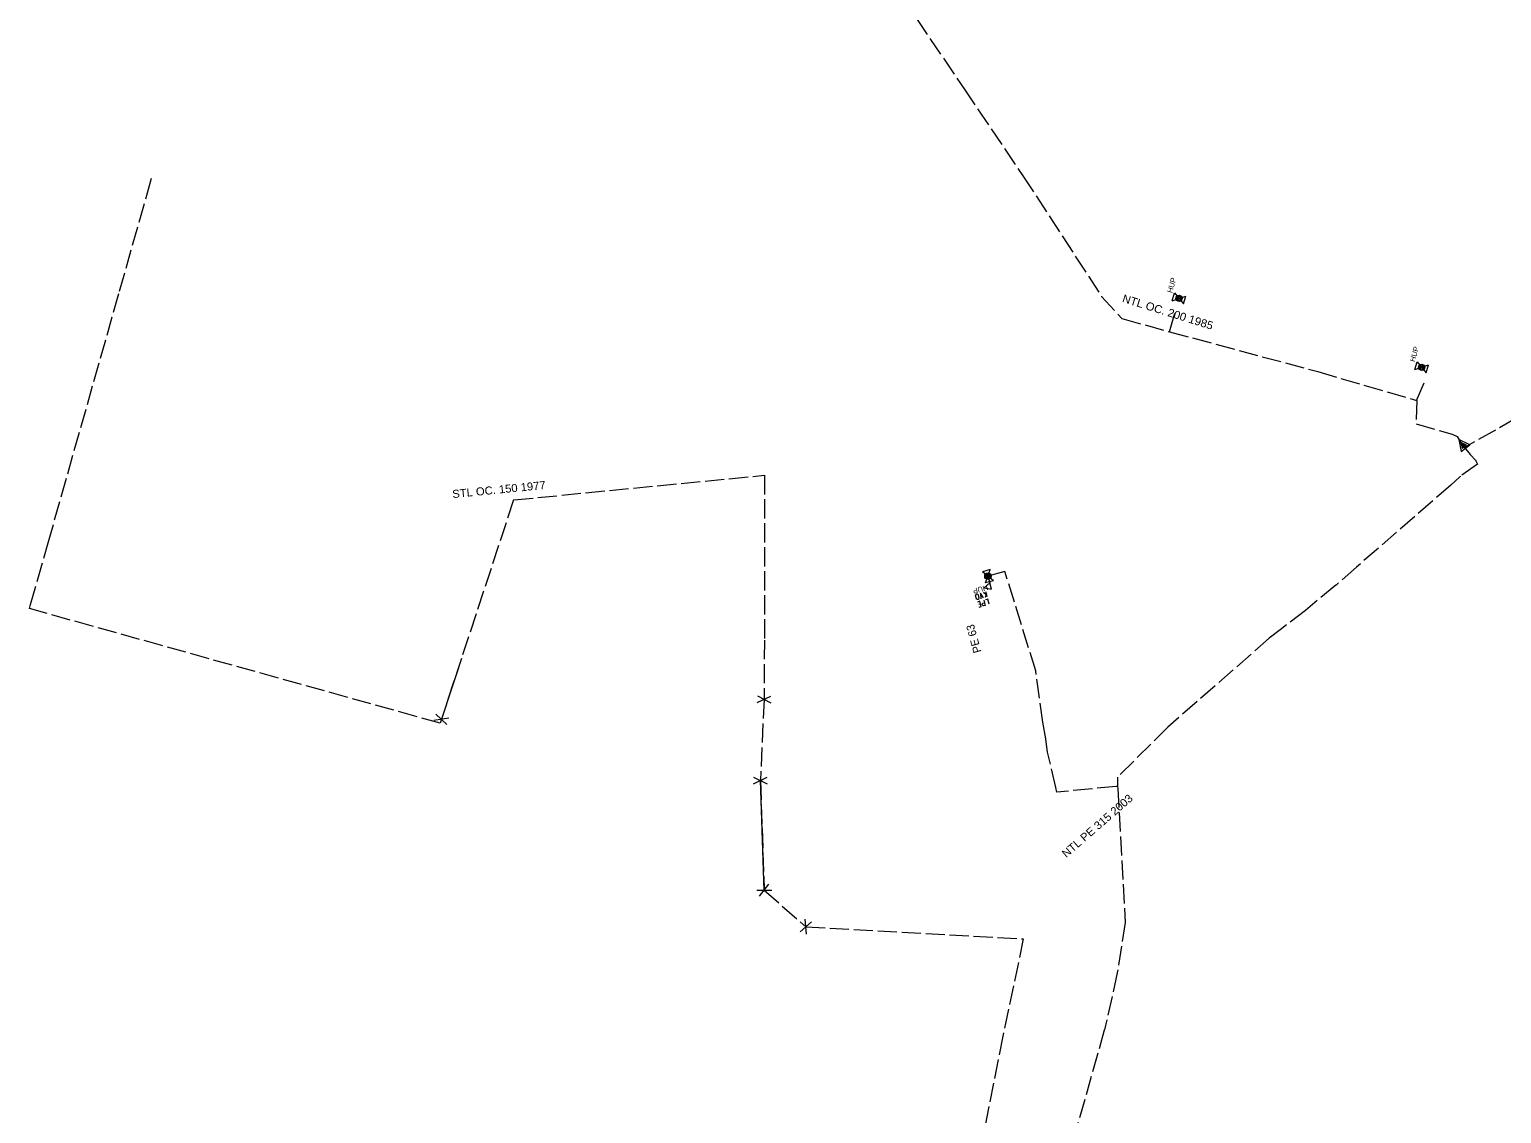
# Model space of a CAD drawing. Extents: x -688140 to -687678, y -1056859 to -1056384.
# Drawn here: x -688140.4 to -688002.5, y -1056593.5 to -1056491.8 of the extents above; entities that cross this region are included whole.
import ezdxf
from ezdxf.enums import TextEntityAlignment as Align

# ---------------------------------------------------------------- set-up
doc = ezdxf.new("R2010")
doc.units = 0
doc.header["$LTSCALE"] = 0.3
doc.linetypes.add('LONG_DASHED', pattern=[7.5, 6, -1.5])
for name, color, linetype, lineweight in [('12', 7, 'Continuous', 13), ('13', 7, 'Continuous', 13), ('25', 7, 'Continuous', 13), ('35', 7, 'LONG_DASHED', 13), ('40', 7, 'LONG_DASHED', 13), ('50', 7, 'LONG_DASHED', 13)]:
    doc.layers.add(name, color=color, linetype=linetype, lineweight=lineweight)
doc.layers.add('15', color=7, linetype='Continuous')

msp = doc.modelspace()

# ---------------------------------------------------------------- linework, layer by layer
at = {"layer": '12'}
for p, q in [((-688033.324, -1056517.252), (-688033.112, -1056516.512)), ((-688033.112, -1056516.512), (-688032.276, -1056517.552)), ((-688033.324, -1056517.252), (-688032.064, -1056516.812)), ((-688032.276, -1056517.552), (-688032.064, -1056516.812)), ((-688010.581, -1056523.712), (-688010.369, -1056522.972)), ((-688010.581, -1056523.712), (-688009.321, -1056523.272)), ((-688010.369, -1056522.972), (-688009.533, -1056524.012)), ((-688009.533, -1056524.012), (-688009.321, -1056523.272)), ((-688050.383, -1056542.452), (-688051.126, -1056542.657)), ((-688050.094, -1056543.503), (-688051.126, -1056542.657)), ((-688050.837, -1056543.708), (-688050.383, -1056542.452)), ((-688050.094, -1056543.503), (-688050.837, -1056543.708)), ((-688050.61, -1056543.08), (-688050.443, -1056543.687)), ((-688051.686, -1056545.201), (-688051.768, -1056544.902)), ((-688051.527, -1056544.836), (-688051.445, -1056545.135)), ((-688051.075, -1056545.614), (-688050.92, -1056545.572)), ((-688050.78, -1056544.838), (-688051.023, -1056544.594)), ((-688050.751, -1056544.716), (-688050.862, -1056545.068)), ((-688050.669, -1056545.015), (-688050.802, -1056544.533)), ((-688051.453, -1056545.708), (-688051.299, -1056545.665))]:
    msp.add_line(p, q, dxfattribs=at)
for points in [[(-688005.451, -1056530.756), (-688006.474, -1056530.268), (-688006.246, -1056531.379)], [(-688005.757, -1056530.78), (-688006.268, -1056530.532), (-688006.15, -1056531.088)], [(-688005.911, -1056530.793), (-688006.166, -1056530.662), (-688006.1, -1056530.941)], [(-688050.443, -1056543.687), (-688050.966, -1056544.163), (-688050.273, -1056544.305)]]:
    msp.add_lwpolyline(points, close=True, dxfattribs=at)
for points in [[(-688051.527, -1056544.836), (-688051.538, -1056544.798), (-688051.562, -1056544.784), (-688051.609, -1056544.765), (-688051.65, -1056544.766), (-688051.698, -1056544.779), (-688051.727, -1056544.787), (-688051.755, -1056544.837), (-688051.769, -1056544.861), (-688051.768, -1056544.902)], [(-688051.445, -1056545.135), (-688051.437, -1056545.164), (-688051.448, -1056545.198), (-688051.479, -1056545.238), (-688051.518, -1056545.248), (-688051.566, -1056545.262), (-688051.595, -1056545.269), (-688051.644, -1056545.242), (-688051.668, -1056545.228), (-688051.686, -1056545.201)], [(-688051.442, -1056545.974), (-688051.23, -1056545.916), (-688051.363, -1056545.434), (-688051.594, -1056545.498)], [(-688051.035, -1056545.116), (-688051.303, -1056544.671), (-688051.286, -1056545.185)], [(-688051.008, -1056545.855), (-688051.062, -1056545.849), (-688051.122, -1056545.782), (-688051.132, -1056545.744), (-688051.118, -1056545.646), (-688051.075, -1056545.614)], [(-688050.987, -1056545.33), (-688050.854, -1056545.813), (-688051.008, -1056545.855)], [(-688050.478, -1056545.709), (-688050.611, -1056545.227), (-688050.832, -1056545.288)]]:
    msp.add_lwpolyline(points, dxfattribs=at)
for centre, radius in [((-688032.694, -1056517.032), 0.297), ((-688032.694, -1056517.032), 0.223), ((-688032.694, -1056517.032), 0.223), ((-688032.694, -1056517.032), 0.112), ((-688009.951, -1056523.492), 0.297), ((-688009.951, -1056523.492), 0.223), ((-688009.951, -1056523.492), 0.223), ((-688009.951, -1056523.492), 0.112), ((-688050.61, -1056543.08), 0.297), ((-688050.61, -1056543.08), 0.223), ((-688050.61, -1056543.08), 0.223), ((-688050.61, -1056543.08), 0.112)]:
    msp.add_circle(centre, radius, dxfattribs=at)
at = {"layer": '13'}
for p, q in [((-688072.232, -1056554.929), (-688070.946, -1056554.331)), ((-688072.216, -1056554.299), (-688070.962, -1056554.961)), ((-688101.129, -1056556.387), (-688102.529, -1056556.605)), ((-688101.319, -1056556.988), (-688102.339, -1056556.004)), ((-688072.569, -1056562.546), (-688071.295, -1056561.922)), ((-688072.565, -1056561.916), (-688071.299, -1056562.552)), ((-688072.281, -1056572.503), (-688070.863, -1056572.529)), ((-688072.011, -1056573.072), (-688071.133, -1056571.96)), ((-688068.206, -1056576.413), (-688067.142, -1056575.477)), ((-688067.623, -1056576.652), (-688067.725, -1056575.238))]:
    msp.add_line(p, q, dxfattribs=at)
at = {"layer": '25'}
for p, q in [((-688099.953, -1056550.795), (-688101.829, -1056556.496)), ((-688071.572, -1056572.516), (-688071.932, -1056562.234))]:
    msp.add_line(p, q, dxfattribs=at)
at = {"layer": '35'}
for points in [[(-688068.5, -1056481.45), (-688066.239, -1056480.491), (-688064.578, -1056479.739), (-688061.036, -1056485.154), (-688060.797, -1056485.528), (-688059.819, -1056487.056), (-688052.842, -1056497.398), (-688047.328, -1056505.525), (-688039.953, -1056516.851), (-688038.044, -1056518.922), (-688033.59, -1056520.156), (-688019.679, -1056523.9), (-688010.809, -1056526.484), (-688010.441, -1056526.59), (-688010.399, -1056526.602), (-688010.483, -1056528.798), (-688007.1, -1056529.75), (-688006.63, -1056529.98), (-688006.34, -1056530.44)], [(-687934.92, -1056483.379), (-687934.48, -1056484.1), (-687931.57, -1056488.93), (-687931.05, -1056489.78), (-687930.64, -1056490.47), (-687940.574, -1056496.498), (-687941.6, -1056497.12), (-687942.464, -1056497.696), (-687944.2, -1056498.69), (-687950.55, -1056502.49), (-687951.37, -1056502.98), (-687952.8, -1056503.81), (-687962, -1056509.53), (-687962.18, -1056509.64), (-687962.19, -1056509.625), (-687963.04, -1056508.39), (-687964.19, -1056506.75), (-687972.1, -1056511.04), (-687973.789, -1056512.111), (-687973.85, -1056512.15), (-687977.61, -1056514.19), (-687978.48, -1056514.66), (-687999.12, -1056527.17), (-688005.94, -1056531)], [(-688005.94, -1056531), (-688006.16, -1056530.67), (-688006.34, -1056530.44)], [(-688005.94, -1056531), (-688005.41, -1056531.66), (-688004.88, -1056532.24), (-688004.873, -1056532.253), (-688004.71, -1056532.56), (-688006.328, -1056533.716), (-688006.39, -1056533.76), (-688007.21, -1056534.53), (-688016.05, -1056542.22), (-688017.98, -1056543.91), (-688018.007, -1056543.932), (-688020.849, -1056546.279), (-688023.211, -1056548.092), (-688024.24, -1056548.9), (-688033.75, -1056557.23), (-688038.45, -1056561.91), (-688038.45, -1056562.58), (-688038.45, -1056562.78), (-688038.44, -1056562.98), (-688037.73, -1056575.55), (-688038.48, -1056580.28), (-688039.69, -1056585.62), (-688039.697, -1056585.644), (-688044.02, -1056600.96)]]:
    msp.add_lwpolyline(points, dxfattribs=at)
at = {"layer": '40'}
for points in [[(-688101.942, -1056556.863), (-688140.445, -1056546.117), (-688140.335, -1056545.73), (-688138.697, -1056539.96), (-688132.001, -1056516.368), (-688129.383, -1056507.137), (-688129.002, -1056505.774)], [(-688095.06, -1056535.93), (-688095.038, -1056535.924), (-688071.56, -1056533.616), (-688071.564, -1056549.067), (-688071.589, -1056554.63), (-688071.932, -1056562.234), (-688071.572, -1056572.516), (-688067.674, -1056575.945), (-688047.289, -1056577.08), (-688049.203, -1056586.191), (-688052.709, -1056603.772), (-688056.92, -1056628.52)], [(-688095.06, -1056535.93), (-688099.953, -1056550.795), (-688101.829, -1056556.496), (-688101.942, -1056556.863)]]:
    msp.add_lwpolyline(points, dxfattribs=at)
at = {"layer": '50'}
for p, q in [((-688033.59, -1056520.156), (-688033.005, -1056518.115)), ((-688010.441, -1056526.59), (-688009.615, -1056524.678))]:
    msp.add_line(p, q, dxfattribs=at)
msp.add_lwpolyline([(-688038.45, -1056562.78), (-688038.576, -1056562.792), (-688044.15, -1056563.33), (-688044.248, -1056562.903), (-688045.01, -1056559.59), (-688045.17, -1056558.37), (-688045.179, -1056558.324), (-688045.47, -1056556.75), (-688046.13, -1056551.95), (-688049.01, -1056542.64), (-688050.61, -1056543.08)], dxfattribs=at)

# ---------------------------------------------------------------- texts
at = {"layer": '12', "width": 0.9}
for rotation, p in [(73.997, (-688033.139, -1056515.864)), (73.997, (-688010.396, -1056522.324)), (195.378, (-688051.376, -1056544.069))]:
    msp.add_text('HUP', height=0.5, rotation=rotation, dxfattribs=at).set_placement(p, align=Align.CENTER)
at = {"layer": '15', "width": 1.05}
for s, rotation, p in [('NTL OC. 200 1985', 342.677, (-688038.074, -1056517.35)), ('STL OC. 150 1977', 5.624, (-688100.773, -1056535.755)), ('NTL PE 315 2003', 41, (-688043.27, -1056569.51))]:
    msp.add_text(s, height=0.75, rotation=rotation, dxfattribs=at).set_placement(p)
at = {"layer": '15'}
msp.add_text('PE 63', height=0.75, rotation=105.376, dxfattribs=at).set_placement((-688051.212, -1056550.161))

doc.saveas('drawing.dxf')
